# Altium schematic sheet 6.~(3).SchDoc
size 420 x 297 mm
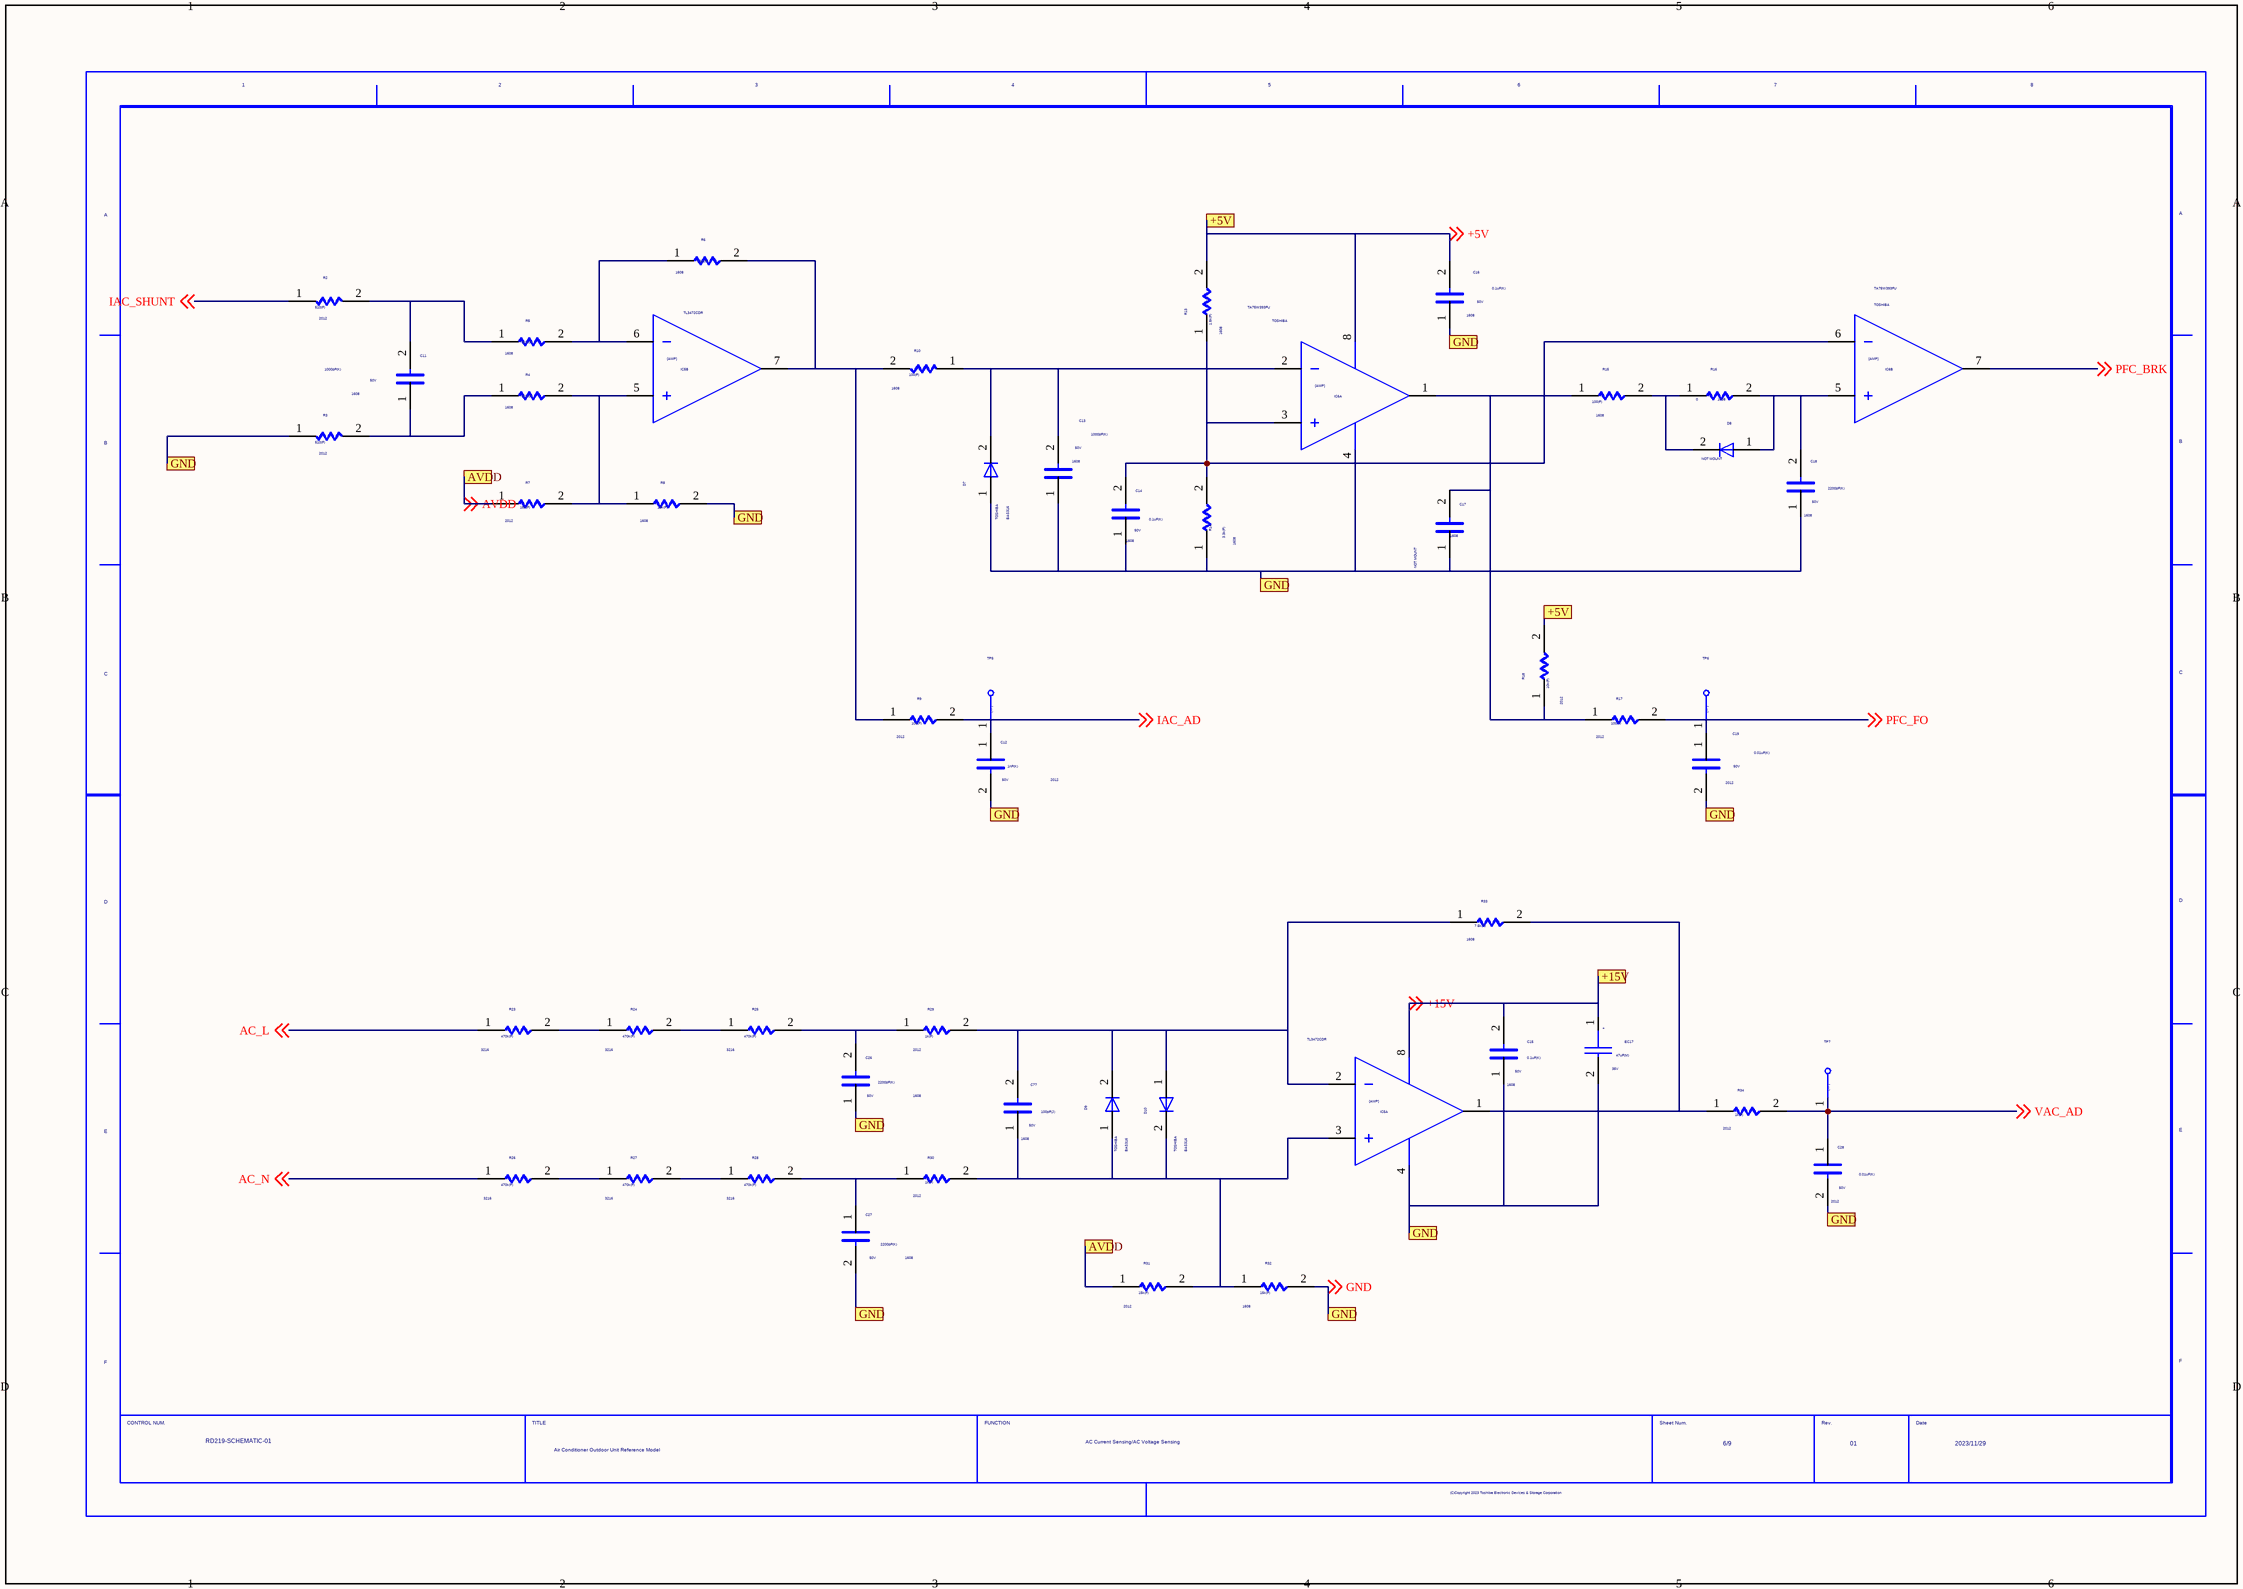
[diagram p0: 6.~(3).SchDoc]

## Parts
C11  SIZECODESMD: 1608  VAL2: 50V  VAL1: 1000pF(K)  (hidden comment: C)
C12  SIZECODESMD: 2012  VAL2: 50V  VAL1: 1nF(K)  (hidden comment: C)
C13  SIZECODESMD: 1608  VAL2: 50V  VAL1: 1000pF(K)  (hidden comment: C)
C14  SIZECODESMD: 1608  VAL2: 50V  VAL1: 0.1uF(K)  (hidden comment: C)
C15  SIZECODESMD: 1608  VAL2: 50V  VAL1: 0.1uF(K)  (hidden comment: C)
C16  SIZECODESMD: 1608  VAL2: 50V  VAL1: 0.1uF(K)  (hidden comment: C)
C17  SIZECODESMD: 1608  NOTMOUNT: NOT MOUNT  (hidden comment: C)
C18  SIZECODESMD: 1608  VAL2: 50V  VAL1: 2200pF(K)  (hidden comment: C)
C19  SIZECODESMD: 2012  VAL2: 50V  VAL1: 0.01uF(K)  (hidden comment: C)
C26  SIZECODESMD: 1608  VAL2: 50V  VAL1: 2200pF(K)  (hidden comment: C)
C27  SIZECODESMD: 1608  VAL2: 50V  VAL1: 2200pF(K)  (hidden comment: C)
C28  SIZECODESMD: 2012  VAL2: 50V  VAL1: 0.01uF(K)  (hidden comment: C)
C77  SIZECODESMD: 1608  VAL2: 50V  VAL1: 100pF(J)  (hidden comment: C)
D7  USERCOMPTEXT3: TOSHIBA  VAL3: BAS316  (hidden comment: D_CUSTOM)
D8  NOTMOUNT: NOT MOUNT  (hidden comment: D_CUSTOM)
D9  USERCOMPTEXT3: TOSHIBA  VAL3: BAS316  (hidden comment: D_CUSTOM)
D10  USERCOMPTEXT3: TOSHIBA  VAL3: BAS316  (hidden comment: D_CUSTOM)
EC17  VAL2: 35V  VAL1: 47uF(M)  (hidden comment: EC)
IC5  VAL1: TL3472CDR  (hidden comment: AMP_1)  (parts A,B of 2)
IC6  USERCOMPTEXT3: TOSHIBA  VAL1: TA75W393FU  (hidden comment: AMP_1)  (parts A,B of 2)
R2  SIZECODESMD: 2012  VAL1: 510(F)  (hidden comment: R)
R3  SIZECODESMD: 2012  VAL1: 510(F)  (hidden comment: R)
R4  VAL1: 510(F)  SIZECODESMD: 1608  (hidden comment: R)
R5  VAL1: 510(F)  SIZECODESMD: 1608  (hidden comment: R)
R6  VAL1: 7.5k(F)  SIZECODESMD: 1608  (hidden comment: R)
R7  VAL1: 15k(F)  SIZECODESMD: 2012  (hidden comment: R)
R8  VAL1: 15k(F)  SIZECODESMD: 1608  (hidden comment: R)
R9  VAL1: 100(F)  SIZECODESMD: 2012  (hidden comment: R)
R10  VAL1: 100(F)  SIZECODESMD: 1608  (hidden comment: R)
R13  VAL1: 1.5k(F)  SIZECODESMD: 1608  (hidden comment: R)
R14  VAL1: 3.3k(F)  SIZECODESMD: 1608  (hidden comment: R)
R15  SIZECODESMD: 1608  VAL1: 100(F)  (hidden comment: R)
R16  SIZECODESMD: 1608  VAL1: 0  (hidden comment: R)
R17  SIZECODESMD: 2012  VAL1: 100(F)  (hidden comment: R)
R18  SIZECODESMD: 2012  VAL1: 10k(F)  (hidden comment: R)
R23  SIZECODESMD: 3216  VAL1: 470k(F)  (hidden comment: R)
R24  SIZECODESMD: 3216  VAL1: 470k(F)  (hidden comment: R)
R25  SIZECODESMD: 3216  VAL1: 470k(F)  (hidden comment: R)
R26  SIZECODESMD: 3216  VAL1: 470k(F)  (hidden comment: R)
R27  SIZECODESMD: 3216  VAL1: 470k(F)  (hidden comment: R)
R28  SIZECODESMD: 3216  VAL1: 470k(F)  (hidden comment: R)
R29  SIZECODESMD: 2012  VAL1: 1k(F)  (hidden comment: R)
R30  SIZECODESMD: 2012  VAL1: 1k(F)  (hidden comment: R)
R31  SIZECODESMD: 2012  VAL1: 15k(F)  (hidden comment: R)
R32  SIZECODESMD: 1608  VAL1: 15k(F)  (hidden comment: R)
R33  SIZECODESMD: 1608  VAL1: 7.5k(F)  (hidden comment: R)
R34  SIZECODESMD: 2012  VAL1: 1k(F)  (hidden comment: R)
TP5  TP  (value not drawn)
TP6  TP  (value not drawn)
TP7  TP  (value not drawn)
U?  DATE: 2023/11/29  TITLE: Air Conditioner Outdoor Unit / Reference Model  SHEETNUMBER: 6/9  DRAWINGNUMBER: RD219-SCHEMATIC-01  FUNCTION: AC Current Sensing/AC Voltage Sensing  REVISION: 01  (hidden comment: WAKU_DEF100)

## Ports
+5V, +15V, AVDD, GND

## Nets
+5V: C16.2 IC6.8 R13.2 R18.2 ; off-sheet +5V, port +5V
+15V: C15.2 EC17.1 IC5.8 ; off-sheet +15V, port +15V
AC_L: R23.1 ; off-sheet AC_L
AC_N: R26.1 ; off-sheet AC_N
AVDD: R7.1 R31.1 ; off-sheet AVDD, port AVDD
GND: C12.2 C13.1 C14.1 C15.1 C16.1 C17.1 C18.1 C19.2 C26.1 C27.2 C28.2 D7.1 EC17.2 IC5.4 IC6.4 R3.1 R8.2 R14.1 R32.2 ; off-sheet GND, port GND
IAC_AD: C12.1 R9.2 TP5.1 ; off-sheet IAC_AD
IAC_SHUNT: R2.1 ; off-sheet IAC_SHUNT
NetC11_1: C11.1 R3.2 R4.1
NetC11_2: C11.2 R2.2 R5.1
NetC13_2: C13.2 D7.2 IC6.2 R10.1
NetC14_2: C14.2 IC6.3 IC6.6 R13.1 R14.2
NetC17_2: C17.2 IC6.1 R15.1 R17.1 R18.1
NetC18_2: C18.2 D8.1 IC6.5 R16.2
NetC26_2: C26.2 R25.2 R29.1
NetC27_1: C27.1 R28.2 R30.1
NetC77_1: C77.1 D9.1 D10.2 IC5.3 R30.2 R31.2 R32.1
NetC77_2: C77.2 D9.2 D10.1 IC5.2 R29.2 R33.1
NetD8_2: D8.2 R15.2 R16.1
NetIC5_1: IC5.1 R33.2 R34.1
NetIC5_5: IC5.5 R4.2 R7.2 R8.1
NetIC5_6: IC5.6 R5.2 R6.1
NetIC5_7: IC5.7 R6.2 R9.1 R10.2
NetR23_2: R23.2 R24.1
NetR24_2: R24.2 R25.1
NetR26_2: R26.2 R27.1
NetR27_2: R27.2 R28.1
PFC_BRK: IC6.7 ; off-sheet PFC_BRK
PFC_FO: C19.1 R17.2 TP6.1 ; off-sheet PFC_FO
VAC_AD: C28.1 R34.2 TP7.1 ; off-sheet VAC_AD

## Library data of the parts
C11 C13 = C_Dup1: OriginalSymbolOrigin: (2540,7620); VAL3: AC0603KRX7R9BB102
C12 = C_Dup1: OriginalSymbolOrigin: (2540,7620); VAL3: AC0805KRX7R9BB102
C14 = C_Dup1: OriginalSymbolOrigin: (2540,7620); COMP: AC0603KRX7R9BB104
C15 = C: OriginalSymbolOrigin: (2540,7620); VAL3: AC0603KRX7R9BB104
C16 = C_Dup1: OriginalSymbolOrigin: (2540,7620); VAL3: AC0603KRX7R9BB104
C17 = C_Dup1: OriginalSymbolOrigin: (2540,7620); COMP: SMT_0603_C
C18 = C_Dup1: OriginalSymbolOrigin: (2540,7620); VAL3: AC0603KRX7R9BB222
C19 = C_Dup1: OriginalSymbolOrigin: (2540,7620); COMP: AC0805KRX7R9BB103
C26 C27 = C: OriginalSymbolOrigin: (2540,7620); VAL3: AC0603KRX7R9BB222
C28 = C: OriginalSymbolOrigin: (2540,7620); VAL3: AC0805KRX7R9BB103
C77 = C: OriginalSymbolOrigin: (2540,7620); VAL3: AC0603JRNPO9BN101
D7 D9 D10 = D_CUSTOM: SAVEAREA0: -1668,-97,14265,7829; SAVECOUNT: 4; TIME: 14:49:55; UPDATEUSER: w20165dm; UPDATETIME: 16:47:49; OriginalSymbolOrigin: (5080,5080)
D8 = D_CUSTOM: SAVEAREA0: -1668,-97,14265,7829; SAVECOUNT: 4; TIME: 14:49:55; UPDATEUSER: w20165dm; UPDATETIME: 16:47:49; OriginalSymbolOrigin: (5080,5080); COMP: 1N4148
EC17 = EC: SAVEAREA0: -1432,-1528,20311,14389; SAVECOUNT: 53; TIME: 15:02:55; UPDATEUSER: w20165dm; UPDATETIME: 16:35:05; OriginalSymbolOrigin: (2540,10160); VAL3: CS1V470M_CRE54
IC5 = AMP_1: SAVEAREA0: -6226,-235,36343,20943; TIME: 17:09:52; UPDATEUSER: w20165dm; SAVECOUNT: 1; OriginalSymbolOrigin: (5080,20320); CaptureCellPackProp: AMP_1A; FUNCN: IC5_1
IC6 = AMP_1: SAVEAREA0: -6226,-235,36343,20943; TIME: 17:09:52; UPDATEUSER: w20165dm; SAVECOUNT: 1; OriginalSymbolOrigin: (5080,20320); CaptureCellPackProp: AMP_1A; FUNCN: IC6_1
R2 R3 = R_Dup1: OriginalSymbolOrigin: (5080,5080); COMP: AC0805FR_07510RL; VAL3: AC0805FR-07510RL; VAL2: 125mW
R4 R5 = R_Dup1: OriginalSymbolOrigin: (5080,5080); VAL3: AC0603FR-07510RL; COMP: AC0603FR_07510RL; VAL2: 100mW
R6 = R_Dup1: OriginalSymbolOrigin: (5080,5080); VAL3: AC0603FR-077K5L; COMP: AC0603FR_077K5L; VAL2: 100mW
R7 = R_Dup1: OriginalSymbolOrigin: (5080,5080); VAL3: AC0805FR-0715KL; COMP: AC0805FR_0715KL; VAL2: 125mW
R8 = R_Dup1: OriginalSymbolOrigin: (5080,5080); VAL3: AC0603FR-0715KL; COMP: AC0603FR_0715KL; VAL2: 100mW
R9 = R_Dup1: OriginalSymbolOrigin: (5080,5080); VAL3: AC0805FR-07100RL; COMP: AC0805FR_07100RL; VAL2: 125mW
R10 = R_Dup1: OriginalSymbolOrigin: (5080,5080); VAL3: AC0603FR-07100RL; COMP: AC0603FR_07100RL; VAL2: 100mW
R13 = R_Dup1: OriginalSymbolOrigin: (5080,5080); VAL3: AC0603FR-071K5L; COMP: AC0603FR_071K5L; VAL2: 100mW
R14 = R_Dup1: OriginalSymbolOrigin: (5080,5080); VAL3: AC0603FR-073K3L; COMP: AC0603FR_073K3L; VAL2: 100mW
R15 = R_Dup1: OriginalSymbolOrigin: (5080,5080); VAL2: 100mW; VAL3: AC0603FR-07100RL; COMP: AC0603FR_07100RL
R16 = R_Dup1: OriginalSymbolOrigin: (5080,5080); VAL2: 100mW; VAL3: AC0603FR-070RL; COMP: AC0603FR_070RL
R17 = R_Dup1: OriginalSymbolOrigin: (5080,5080); VAL2: 125mW; VAL3: AC0805FR-07100RL; COMP: AC0805FR_07100RL
R18 = R_Dup1: OriginalSymbolOrigin: (5080,5080); VAL2: 125mW; VAL3: AC0805FR-0710KL; COMP: AC0805FR_0710KL
R23 = R: OriginalSymbolOrigin: (5080,5080); VAL3: AC1206FR-07470KL; VAL2: 125mW; COMP: AC1206FR_07470KL
R24 = R: OriginalSymbolOrigin: (5080,5080); COMP: AC1206FR_07470KL; VAL3: AC1206FR-07470KL; VAL2: 250mW
R25 = R: OriginalSymbolOrigin: (5080,5080); VAL3: AC1206FR-07470KL; VAL2: 250mW; COMP: AC1206FR_07470KL
R26-R28 = R: OriginalSymbolOrigin: (5080,5080); VAL2: 250mW; VAL3: AC1206FR-07470KL; COMP: AC1206FR_07470KL
R29 R30 R34 = R: OriginalSymbolOrigin: (5080,5080); VAL2: 125mW; VAL3: AC0805FR-071KL; COMP: AC0805FR_071KL
R31 = R: OriginalSymbolOrigin: (5080,5080); VAL3: AC0805FR-0715KL; VAL2: 125mW; COMP: AC0805FR_0715KL
R32 = R: OriginalSymbolOrigin: (5080,5080); VAL3: AC0603FR-0715KL; VAL2: 100mW; COMP: AC0805FR_0715KL
R33 = R: OriginalSymbolOrigin: (5080,5080); VAL3: AC0603FR-077K5L; VAL2: 100mW; COMP: AC0603FR_077K5L
TP5 = TP: TIME: 16:12:21; UPDATEUSER: fukuda-y; UPDATETIME: 16:18:11; SAVECOUNT: 2; SAVEAREA0: -242,-92,12810,7836; OriginalSymbolOrigin: (0,7620); COMPCOMMENT: IAC_AD; VAL3: ZXD
TP6 = TP: TIME: 16:12:21; UPDATEUSER: fukuda-y; UPDATETIME: 16:18:11; SAVECOUNT: 2; SAVEAREA0: -242,-92,12810,7836; OriginalSymbolOrigin: (0,7620); VAL3: ZXD; COMPCOMMENT: PFC_FO
TP7 = TP_Dup1: TIME: 16:12:21; UPDATEUSER: fukuda-y; UPDATETIME: 16:18:11; SAVECOUNT: 2; SAVEAREA0: -242,-92,12810,7836; OriginalSymbolOrigin: (0,7620); VAL3: ZXD; COMPCOMMENT: VAC_AD
U? = WAKU_DEF100: PLOTTIME: HH:MM; SAVEAREA0: -45080,-4508,463680,304612; TIME: 15:33:48; UPDATEUSER: sptcae13; UPDATETIME: 08:19:30; SAVECOUNT: 8; OriginalSymbolOrigin: (10160,284480)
